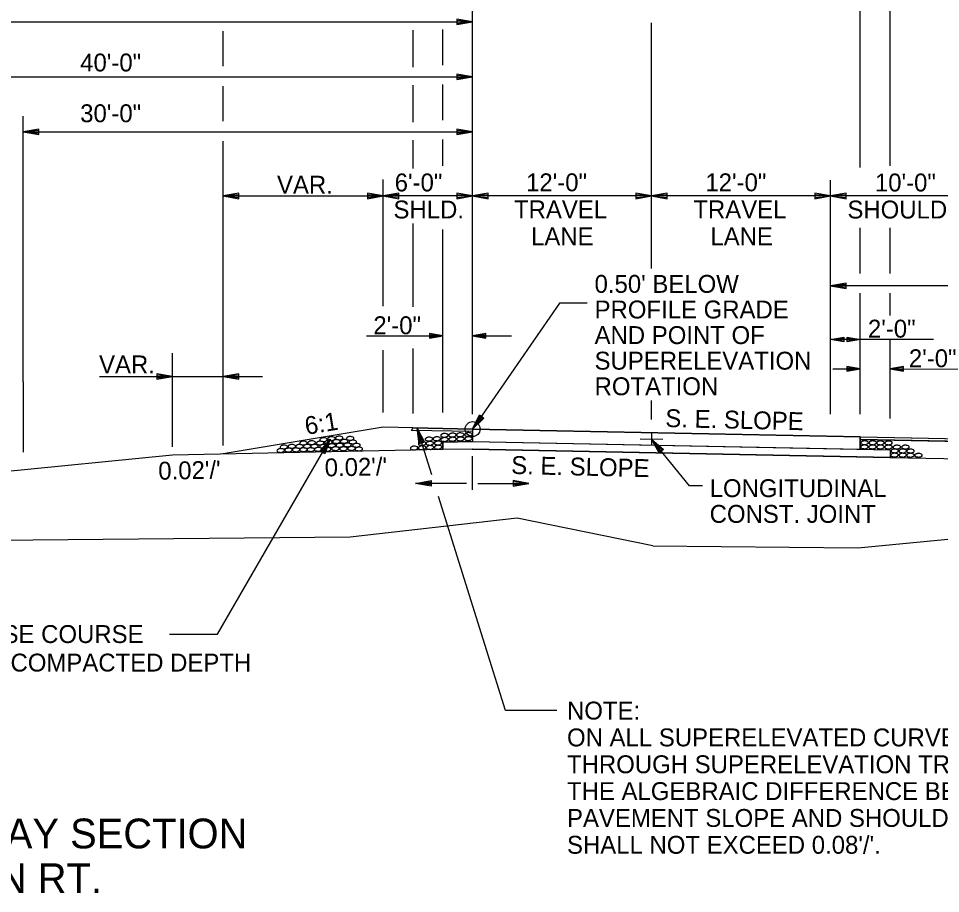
# Model space of a CAD drawing. Extents: x 1734743 to 1735935, y 759845 to 763831.
# Drawn here: x 1735753.6 to 1735815.4, y 760275.4 to 760334.1 of the extents above; entities that cross this region are included whole.
import ezdxf

# ---------------------------------------------------------------- set-up
doc = ezdxf.new("R2010")
doc.units = 0
for name, color, linetype in [('1', 7, 'Continuous'), ('10', 7, 'Continuous'), ('11', 7, 'Continuous'), ('19', 7, 'Continuous'), ('7', 7, 'Continuous'), ('8', 7, 'Continuous'), ('9', 7, 'Continuous'), ('Level 1', 7, 'Continuous'), ('R_Draft', 7, 'Continuous'), ('R_Prop Surface', 7, 'Continuous')]:
    doc.layers.add(name, color=color, linetype=linetype)

# ---------------------------------------------------------------- blocks, each defined once
blk = doc.blocks.new('TM')
at = {"layer": '8'}
for p, q in [((-120.309, 21.181), (-119.787, -20.829)), ((0, 0), (-120.309, 21.181)), ((-31.382, 2.945), (-120.176, 10.512)), ((-119.787, -20.829), (0, 0)), ((-119.911, -10.826), (-31.307, -3.057))]:
    blk.add_line(p, q, dxfattribs=at)
blk = doc.blocks.new('ROCKS')
at = {"layer": '1'}
blk.add_spline([(0.013, 0.06), (0.053, 0.053), (0.107, 0.033), (0.133, 0.013), (0.133, -0.007), (0.12, -0.033), (0.107, -0.04), (0.073, -0.053), (0.033, -0.067), (0.013, -0.067), (-0.02, -0.06), (-0.06, -0.053), (-0.087, -0.047), (-0.113, -0.02), (-0.113, -0.007), (-0.107, 0.02), (-0.087, 0.033), (-0.067, 0.047), (-0.033, 0.053), (-0.02, 0.06), (0.013, 0.06)], degree=3, dxfattribs=at)

msp = doc.modelspace()

# ---------------------------------------------------------------- linework, layer by layer
at = {"layer": '11'}
for p, q in [((1735787.06, 760300.552), (1735775.872, 760299.284)), ((1735796.16, 760298.685), (1735787.06, 760300.552)), ((1735775.872, 760299.284), (1735746.283, 760298.983)), ((1735809.903, 760298.57), (1735818.755, 760299.405)), ((1735796.16, 760298.685), (1735809.903, 760298.57))]:
    msp.add_line(p, q, dxfattribs=at)
at = {"layer": '19'}
for p, q in [((1735812.065, 760324.185), (1735812.065, 760345.329)), ((1735784.076, 760312.704), (1735784.076, 760335.65)), ((1735810.065, 760324.054), (1735810.065, 760335.441)), ((1735784.076, 760326.452), (1735784.076, 760334.485)), ((1735704.076, 760333.825), (1735784.076, 760333.825)), ((1735783.026, 760334.009), (1735783.026, 760333.642)), ((1735784.076, 760333.825), (1735783.026, 760334.009)), ((1735783.796, 760333.852), (1735783.026, 760333.913)), ((1735783.026, 760333.642), (1735784.076, 760333.825)), ((1735783.026, 760333.729), (1735783.796, 760333.799)), ((1735767.346, 760330.866), (1735767.346, 760333.195)), ((1735780.08, 760330.872), (1735780.08, 760333.281)), ((1735780.08, 760330.798), (1735780.08, 760333.127)), ((1735782.077, 760330.915), (1735782.077, 760333.324)), ((1735744.076, 760330.139), (1735784.076, 760330.139)), ((1735783.026, 760330.323), (1735783.026, 760329.955)), ((1735784.076, 760330.139), (1735783.026, 760330.323)), ((1735783.796, 760330.165), (1735783.026, 760330.226)), ((1735783.026, 760329.955), (1735784.076, 760330.139)), ((1735783.026, 760330.043), (1735783.796, 760330.113)), ((1735767.346, 760327.179), (1735767.346, 760329.508)), ((1735780.08, 760327.186), (1735780.08, 760329.594)), ((1735780.08, 760327.111), (1735780.08, 760329.44)), ((1735782.077, 760327.228), (1735782.077, 760329.637)), ((1735753.951, 760309.697), (1735753.951, 760327.498)), ((1735755.001, 760326.636), (1735753.951, 760326.452)), ((1735753.951, 760326.452), (1735755.001, 760326.268)), ((1735753.951, 760326.452), (1735784.076, 760326.452)), ((1735755.001, 760326.539), (1735754.231, 760326.478)), ((1735754.231, 760326.426), (1735755.001, 760326.356)), ((1735755.001, 760326.268), (1735755.001, 760326.636)), ((1735783.026, 760326.636), (1735783.026, 760326.268)), ((1735784.076, 760326.452), (1735783.026, 760326.636)), ((1735783.796, 760326.478), (1735783.026, 760326.54)), ((1735783.026, 760326.268), (1735784.076, 760326.452)), ((1735783.026, 760326.356), (1735783.796, 760326.426)), ((1735767.346, 760311.729), (1735767.346, 760325.822)), ((1735780.08, 760324.123), (1735780.08, 760325.89)), ((1735780.08, 760324.005), (1735780.08, 760325.754)), ((1735782.077, 760324.166), (1735782.077, 760325.933)), ((1735768.396, 760322.337), (1735767.346, 760322.153)), ((1735767.346, 760322.153), (1735768.396, 760321.97)), ((1735768.396, 760322.241), (1735767.626, 760322.18)), ((1735767.626, 760322.127), (1735768.396, 760322.057)), ((1735768.396, 760321.97), (1735768.396, 760322.337)), ((1735777.026, 760322.337), (1735777.026, 760321.97)), ((1735778.076, 760322.154), (1735777.026, 760322.337)), ((1735777.796, 760322.18), (1735777.026, 760322.241)), ((1735777.026, 760321.97), (1735778.076, 760322.154)), ((1735777.026, 760322.057), (1735777.796, 760322.127)), ((1735779.126, 760322.336), (1735778.076, 760322.153)), ((1735778.076, 760322.153), (1735779.126, 760321.969)), ((1735779.126, 760322.249), (1735778.356, 760322.179)), ((1735778.356, 760322.127), (1735779.126, 760322.065)), ((1735779.126, 760321.969), (1735779.126, 760322.336)), ((1735783.026, 760322.337), (1735783.026, 760321.969)), ((1735784.076, 760322.153), (1735783.026, 760322.337)), ((1735783.796, 760322.179), (1735783.026, 760322.24)), ((1735783.026, 760321.969), (1735784.076, 760322.153)), ((1735783.026, 760322.057), (1735783.796, 760322.127)), ((1735785.126, 760322.336), (1735784.076, 760322.153)), ((1735784.076, 760322.153), (1735785.126, 760321.969)), ((1735785.126, 760322.24), (1735784.356, 760322.179)), ((1735784.356, 760322.127), (1735785.126, 760322.056)), ((1735785.126, 760321.969), (1735785.126, 760322.336)), ((1735795.026, 760322.337), (1735795.026, 760321.969)), ((1735796.076, 760322.153), (1735795.026, 760322.337)), ((1735795.796, 760322.179), (1735795.026, 760322.24)), ((1735795.026, 760321.969), (1735796.076, 760322.153)), ((1735795.026, 760322.057), (1735795.796, 760322.127)), ((1735797.126, 760322.336), (1735796.076, 760322.153)), ((1735796.076, 760322.153), (1735797.126, 760321.969)), ((1735797.126, 760322.24), (1735796.356, 760322.179)), ((1735796.356, 760322.127), (1735797.126, 760322.056)), ((1735797.126, 760321.969), (1735797.126, 760322.336)), ((1735807.026, 760322.337), (1735807.026, 760321.969)), ((1735808.076, 760322.153), (1735807.026, 760322.337)), ((1735807.796, 760322.179), (1735807.026, 760322.24)), ((1735807.026, 760321.969), (1735808.076, 760322.153)), ((1735807.026, 760322.057), (1735807.796, 760322.127)), ((1735809.126, 760322.336), (1735808.076, 760322.153)), ((1735808.076, 760322.153), (1735809.126, 760321.969)), ((1735809.126, 760322.24), (1735808.356, 760322.179)), ((1735808.356, 760322.127), (1735809.126, 760322.056)), ((1735809.126, 760321.969), (1735809.126, 760322.336)), ((1735780.08, 760314.717), (1735780.08, 760320.307)), ((1735782.077, 760307.636), (1735782.077, 760319.912)), ((1735810.065, 760316.957), (1735810.065, 760320.014)), ((1735812.065, 760316.957), (1735812.065, 760320.014)), ((1735809.126, 760316.308), (1735808.076, 760316.124)), ((1735808.076, 760316.124), (1735809.126, 760315.94)), ((1735809.126, 760316.212), (1735808.356, 760316.15)), ((1735808.356, 760316.098), (1735809.126, 760316.028)), ((1735809.126, 760315.94), (1735809.126, 760316.308)), ((1735810.068, 760313.588), (1735810.068, 760315.646)), ((1735812.068, 760314.129), (1735812.068, 760315.646)), ((1735810.068, 760307.517), (1735810.068, 760313.588)), ((1735776.968, 760312.766), (1735782.077, 760312.766)), ((1735781.182, 760312.923), (1735781.182, 760312.61)), ((1735782.077, 760312.766), (1735781.182, 760312.923)), ((1735781.838, 760312.788), (1735781.182, 760312.841)), ((1735781.182, 760312.61), (1735782.077, 760312.766)), ((1735781.182, 760312.684), (1735781.838, 760312.744)), ((1735784.971, 760312.924), (1735784.076, 760312.767)), ((1735784.076, 760312.767), (1735786.681, 760312.766)), ((1735784.076, 760312.767), (1735784.971, 760312.611)), ((1735784.971, 760312.849), (1735784.315, 760312.79)), ((1735784.315, 760312.745), (1735784.971, 760312.693)), ((1735784.971, 760312.611), (1735784.971, 760312.924)), ((1735808.076, 760312.537), (1735808.971, 760312.694)), ((1735814.973, 760312.537), (1735808.076, 760312.537)), ((1735808.971, 760312.381), (1735808.076, 760312.537)), ((1735808.315, 760312.559), (1735808.971, 760312.612)), ((1735808.971, 760312.455), (1735808.315, 760312.515)), ((1735808.971, 760312.694), (1735808.971, 760312.381)), ((1735809.182, 760312.38), (1735809.182, 760312.694)), ((1735809.182, 760312.694), (1735810.076, 760312.537)), ((1735809.182, 760312.619), (1735809.838, 760312.559)), ((1735810.076, 760312.537), (1735809.182, 760312.38)), ((1735809.838, 760312.515), (1735809.182, 760312.462)), ((1735812.068, 760307.235), (1735812.068, 760312.499)), ((1735763.948, 760305.323), (1735763.948, 760311.62)), ((1735767.346, 760305.431), (1735767.346, 760311.729)), ((1735778.076, 760307.636), (1735778.076, 760311.818)), ((1735780.08, 760307.577), (1735780.08, 760311.917)), ((1735763.948, 760305.323), (1735763.948, 760311.081)), ((1735808.231, 760310.553), (1735810.068, 760310.553)), ((1735809.174, 760310.709), (1735809.174, 760310.396)), ((1735810.068, 760310.553), (1735809.174, 760310.709)), ((1735809.83, 760310.575), (1735809.174, 760310.627)), ((1735809.174, 760310.396), (1735810.068, 760310.553)), ((1735809.174, 760310.471), (1735809.83, 760310.53)), ((1735812.963, 760310.71), (1735812.068, 760310.554)), ((1735812.068, 760310.554), (1735817.745, 760310.55)), ((1735812.068, 760310.554), (1735812.963, 760310.397)), ((1735812.963, 760310.636), (1735812.307, 760310.576)), ((1735812.307, 760310.532), (1735812.963, 760310.479)), ((1735812.963, 760310.397), (1735812.963, 760310.71)), ((1735759.049, 760310.046), (1735769.982, 760310.046)), ((1735762.898, 760310.23), (1735762.898, 760309.862)), ((1735763.948, 760310.046), (1735762.898, 760310.23)), ((1735763.668, 760310.072), (1735762.898, 760310.133)), ((1735762.898, 760309.862), (1735763.948, 760310.046)), ((1735762.898, 760309.95), (1735763.668, 760310.02)), ((1735768.396, 760310.229), (1735767.346, 760310.046)), ((1735767.346, 760310.046), (1735768.396, 760309.862)), ((1735768.396, 760310.133), (1735767.626, 760310.072)), ((1735767.626, 760310.02), (1735768.396, 760309.949)), ((1735768.396, 760309.862), (1735768.396, 760310.229)), ((1735784.076, 760306.52), (1735784.54, 760307.48)), ((1735784.835, 760307.264), (1735784.076, 760306.52)), ((1735784.222, 760306.758), (1735784.613, 760307.421)), ((1735784.764, 760307.314), (1735784.262, 760306.73)), ((1735784.54, 760307.48), (1735784.835, 760307.264)), ((1735778.076, 760306.64), (1735767.346, 760304.852)), ((1735784.076, 760306.52), (1735778.076, 760306.64)), ((1735780.491, 760305.54), (1735780.357, 760306.594)), ((1735780.357, 760306.594), (1735780.841, 760305.644)), ((1735784.076, 760306.353), (1735779.982, 760306.435)), ((1735780.573, 760305.566), (1735780.412, 760306.319)), ((1735780.459, 760306.334), (1735780.75, 760305.622)), ((1735784.076, 760306.52), (1735818.08, 760305.84)), ((1735784.076, 760306.52), (1735784.076, 760305.686)), ((1735810.068, 760306), (1735810.068, 760305.166)), ((1735766.973, 760292.777), (1735774.532, 760305.855)), ((1735773.85, 760305.04), (1735774.532, 760305.855)), ((1735773.925, 760304.997), (1735774.368, 760305.628)), ((1735774.411, 760305.603), (1735774.087, 760304.905)), ((1735774.532, 760305.855), (1735774.165, 760304.854)), ((1735780.841, 760305.644), (1735780.491, 760305.54)), ((1735784.076, 760305.686), (1735782.077, 760305.646)), ((1735782.077, 760305.646), (1735782.077, 760305.146)), ((1735784.076, 760305.686), (1735810.068, 760305.166)), ((1735796.593, 760304.925), (1735796.076, 760305.854)), ((1735796.076, 760305.854), (1735796.879, 760305.152)), ((1735796.66, 760304.98), (1735796.23, 760305.619)), ((1735796.268, 760305.651), (1735796.803, 760305.098)), ((1735810.068, 760305.833), (1735818.164, 760305.671)), ((1735763.948, 760304.784), (1735741.106, 760302.499)), ((1735763.948, 760304.784), (1735741.106, 760302.499)), ((1735782.077, 760305.146), (1735763.948, 760304.784)), ((1735774.165, 760304.854), (1735773.85, 760305.04)), ((1735784.04, 760305.185), (1735782.04, 760305.145)), ((1735784.076, 760305.186), (1735782.077, 760305.146)), ((1735784.04, 760305.185), (1735812.05, 760304.625)), ((1735784.04, 760304.713), (1735784.04, 760302.459)), ((1735796.879, 760305.152), (1735796.593, 760304.925)), ((1735810.068, 760305.166), (1735812.068, 760305.126)), ((1735812.068, 760305.126), (1735812.068, 760304.626)), ((1735812.05, 760304.625), (1735830.581, 760304.255)), ((1735783.661, 760302.876), (1735780.24, 760302.876)), ((1735784.419, 760302.876), (1735787.84, 760302.876)), ((1735763.741, 760292.777), (1735766.973, 760292.777))]:
    msp.add_line(p, q, dxfattribs=at)
for points in [[(1735784.076, 760306.353), (1735779.982, 760306.435), (1735779.982, 760306.435), (1735780.077, 760306.6), (1735780.077, 760306.6), (1735780.077, 760306.6), (1735784.076, 760306.52), (1735784.076, 760306.52), (1735784.076, 760306.52), (1735784.076, 760306.353), (1735784.076, 760306.353), (1735784.076, 760306.353)], [(1735818.164, 760305.671), (1735810.068, 760305.833), (1735810.068, 760305.833), (1735810.068, 760306), (1735810.068, 760306), (1735810.068, 760306), (1735818.08, 760305.84), (1735818.08, 760305.84), (1735818.08, 760305.84), (1735818.164, 760305.671), (1735818.164, 760305.671), (1735818.164, 760305.671)], [(1735782.077, 760305.146), (1735782.077, 760305.646), (1735784.076, 760305.686), (1735812.068, 760305.126), (1735812.068, 760304.626), (1735812.068, 760304.626), (1735812.068, 760304.626), (1735784.076, 760305.186), (1735782.077, 760305.146)], [(1735799.482, 760302.726), (1735798.606, 760302.726), (1735796.076, 760305.854)]]:
    msp.add_lwpolyline(points, dxfattribs=at)
msp.add_lwpolyline([(1735810.068, 760306), (1735784.076, 760306.52), (1735784.076, 760305.686), (1735810.068, 760305.166)], close=True, dxfattribs=at)
at = {"layer": '7'}
for p, q in [((1735796.076, 760317.3), (1735796.076, 760333.765)), ((1735796.076, 760307.168), (1735796.076, 760308.435))]:
    msp.add_line(p, q, dxfattribs=at)
at = {"layer": '9'}
for p, q in [((1735784.076, 760307.518), (1735784.076, 760326.452)), ((1735778.076, 760314.759), (1735778.076, 760323.264)), ((1735808.076, 760307.512), (1735808.076, 760323.203)), ((1735767.346, 760322.153), (1735778.076, 760322.153)), ((1735784.076, 760322.153), (1735778.076, 760322.153)), ((1735796.076, 760322.153), (1735784.076, 760322.153)), ((1735808.076, 760322.153), (1735796.076, 760322.153)), ((1735818.066, 760322.153), (1735808.076, 760322.153)), ((1735838.118, 760316.124), (1735808.076, 760316.124)), ((1735753.951, 760309.697), (1735753.951, 760304.969)), ((1735781.336, 760303.45), (1735780.357, 760306.594)), ((1735786.28, 760287.646), (1735781.79, 760301.998))]:
    msp.add_line(p, q, dxfattribs=at)
for points in [[(1735791.752, 760314.963), (1735789.907, 760314.963), (1735784.076, 760306.52)], [(1735789.714, 760287.646), (1735786.28, 760287.646)]]:
    msp.add_lwpolyline(points, dxfattribs=at)
msp.add_circle((1735784.076, 760306.52), 0.5, dxfattribs=at)
at = {"layer": 'R_Draft'}
for p, q in [((1735796.076, 760306.229), (1735796.076, 760305.478)), ((1735795.305, 760305.869), (1735796.824, 760305.839))]:
    msp.add_line(p, q, dxfattribs=at)
at = {"layer": 'R_Prop Surface'}
msp.add_line((1735780.077, 760306.6), (1735779.982, 760306.435), dxfattribs=at)

# ---------------------------------------------------------------- block references
at = {"layer": '19', "xscale": 0.008761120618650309}
for p, yscale, rotation in [((1735780.236, 760302.871), -0.008761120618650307, -179.20057588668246), ((1735787.84, 760302.871), 0.008761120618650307, -0.7994241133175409)]:
    msp.add_blockref('TM', p, dxfattribs=dict(at, yscale=yscale, rotation=rotation))
at = {"layer": 'Level 1'}
for p, xscale, yscale, rotation in [((1735774.066, 760305.82), 2.011654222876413, 2.011654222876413, 1.8263814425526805), ((1735774.594, 760305.892), 2.011654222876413, 2.011654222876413, 1.8263814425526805), ((1735775.112, 760305.931), 2.011654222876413, 2.011654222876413, 1.8263814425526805), ((1735775.851, 760305.903), 2.011654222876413, 2.011654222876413, 1.8263814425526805), ((1735781.129, 760305.86), 2.0116542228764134, 2.011654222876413, 3.8532744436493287), ((1735781.656, 760305.878), 2.0116542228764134, 2.011654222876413, 3.8532744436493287), ((1735782.166, 760306.108), 2.0116542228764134, 2.011654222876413, 3.8532744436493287), ((1735782.171, 760305.828), 2.0116542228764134, 2.011654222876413, 3.8532744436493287), ((1735782.709, 760306.128), 2.0116542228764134, 2.011654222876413, 3.8532744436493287), ((1735782.713, 760305.848), 2.0116542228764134, 2.011654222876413, 3.8532744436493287), ((1735783.23, 760306.146), 2.0116542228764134, 2.011654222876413, 3.8532744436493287), ((1735783.235, 760305.866), 2.0116542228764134, 2.011654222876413, 3.8532744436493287), ((1735783.773, 760306.165), 2.0116542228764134, 2.011654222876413, 3.8532744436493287), ((1735783.777, 760305.885), 2.0116542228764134, 2.011654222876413, 3.8532744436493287), ((1735771.406, 760305.329), 2.011654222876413, 2.011654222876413, 1.8263814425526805), ((1735771.931, 760305.369), 2.011654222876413, 2.011654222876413, 1.8263814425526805), ((1735772.443, 760305.369), 2.011654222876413, 2.011654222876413, 1.8263814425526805), ((1735772.709, 760305.592), 2.011654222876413, 2.011654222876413, 1.8263814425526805), ((1735772.953, 760305.369), 2.011654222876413, 2.011654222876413, 1.8263814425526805), ((1735773.263, 760305.616), 2.011654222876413, 2.011654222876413, 1.8263814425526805), ((1735773.446, 760305.375), 2.011654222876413, 2.011654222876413, 1.8263814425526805), ((1735773.698, 760305.17), 2.011654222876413, 2.011654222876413, 1.8263814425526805), ((1735773.837, 760305.589), 2.011654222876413, 2.011654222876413, 1.8263814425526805), ((1735774.054, 760305.375), 2.011654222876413, 2.011654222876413, 1.8263814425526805), ((1735774.306, 760305.17), 2.011654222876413, 2.011654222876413, 1.8263814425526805), ((1735774.39, 760305.637), 2.011654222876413, 2.011654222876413, 1.8263814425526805), ((1735774.608, 760305.422), 2.011654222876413, 2.011654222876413, 1.8263814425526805), ((1735774.86, 760305.217), 2.011654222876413, 2.011654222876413, 1.8263814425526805), ((1735774.923, 760305.696), 2.011654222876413, 2.011654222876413, 1.8263814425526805), ((1735775.142, 760305.442), 2.011654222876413, 2.011654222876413, 1.8263814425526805), ((1735775.4, 760305.205), 2.011654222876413, 2.011654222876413, 1.8263814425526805), ((1735775.45, 760305.71), 2.011654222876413, 2.011654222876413, 1.8263814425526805), ((1735775.673, 760305.467), 2.011654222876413, 2.011654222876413, 1.8263814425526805), ((1735775.936, 760305.229), 2.011654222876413, 2.011654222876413, 1.8263814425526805), ((1735776.024, 760305.663), 2.011654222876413, 2.011654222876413, 1.8263814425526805), ((1735776.269, 760305.445), 2.011654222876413, 2.011654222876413, 1.8263814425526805), ((1735776.432, 760305.192), 2.011654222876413, 2.011654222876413, 1.8263814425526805), ((1735780.134, 760305.256), 2.0116542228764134, 2.011654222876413, 3.8532744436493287), ((1735780.672, 760305.555), 2.0116542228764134, 2.011654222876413, 3.8532744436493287), ((1735780.677, 760305.275), 2.0116542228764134, 2.011654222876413, 3.8532744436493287), ((1735781.193, 760305.574), 2.0116542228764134, 2.011654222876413, 3.8532744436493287), ((1735781.198, 760305.294), 2.0116542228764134, 2.011654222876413, 3.8532744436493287), ((1735781.736, 760305.593), 2.0116542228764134, 2.011654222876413, 3.8532744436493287), ((1735781.74, 760305.313), 2.0116542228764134, 2.011654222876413, 3.8532744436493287), ((1735810.329, 760305.334), 2.011654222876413, 2.011654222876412, 1.33680650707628), ((1735810.337, 760305.614), 2.011654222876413, 2.011654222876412, 1.33680650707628), ((1735810.873, 760305.33), 2.011654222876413, 2.011654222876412, 1.33680650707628), ((1735810.88, 760305.61), 2.011654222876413, 2.011654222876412, 1.33680650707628), ((1735811.394, 760305.325), 2.011654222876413, 2.011654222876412, 1.33680650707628), ((1735811.402, 760305.605), 2.011654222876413, 2.011654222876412, 1.33680650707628), ((1735811.937, 760305.321), 2.011654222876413, 2.011654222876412, 1.33680650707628), ((1735811.945, 760305.601), 2.011654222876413, 2.011654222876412, 1.33680650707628), ((1735812.505, 760305.321), 2.011654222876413, 2.011654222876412, 1.33680650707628), ((1735813.075, 760305.321), 2.011654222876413, 2.011654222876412, 1.33680650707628), ((1735771.186, 760305.092), 2.011654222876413, 2.011654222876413, 1.8263814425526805), ((1735771.716, 760305.122), 2.011654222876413, 2.011654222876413, 1.8263814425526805), ((1735772.215, 760305.136), 2.011654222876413, 2.011654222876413, 1.8263814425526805), ((1735772.711, 760305.146), 2.011654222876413, 2.011654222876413, 1.8263814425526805), ((1735773.208, 760305.154), 2.011654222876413, 2.011654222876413, 1.8263814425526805), ((1735812.346, 760304.785), 2.011654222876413, 2.011654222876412, 1.33680650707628), ((1735812.354, 760305.065), 2.011654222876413, 2.011654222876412, 1.33680650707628), ((1735812.89, 760304.781), 2.011654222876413, 2.011654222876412, 1.33680650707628), ((1735812.897, 760305.061), 2.011654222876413, 2.011654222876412, 1.33680650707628), ((1735813.411, 760304.776), 2.011654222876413, 2.011654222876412, 1.33680650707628), ((1735813.419, 760305.056), 2.011654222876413, 2.011654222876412, 1.33680650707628), ((1735813.954, 760304.772), 2.011654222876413, 2.011654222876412, 1.33680650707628)]:
    msp.add_blockref('ROCKS', p, dxfattribs=dict(at, xscale=xscale, yscale=yscale, rotation=rotation))

# ---------------------------------------------------------------- texts
at = {"layer": '10'}
for s, height, p in [('VAR.', 1.2, (1735770.96, 760322.307)), ('6\'-0"', 1.2, (1735778.851, 760322.459)), ('10\'-0"', 1.2, (1735811.047, 760322.456)), ('SHLD.', 1.2, (1735778.771, 760320.646)), ('SHOULDER', 1.2, (1735809.204, 760320.644)), ("0.50' BELOW", 1.2, (1735792.252, 760315.658)), ('PROFILE GRADE', 1.2, (1735792.252, 760313.941)), ('AND POINT OF', 1.2, (1735792.252, 760312.225)), ('SUPERELEVATION', 1.2, (1735792.252, 760310.509)), ('ROTATION  ', 1.2, (1735792.252, 760308.793)), ('NOTE:', 1.2, (1735790.404, 760287.046)), ('ON ALL SUPERELEVATED CURVES AND', 1.2, (1735790.404, 760285.246)), ('THROUGH SUPERELEVATION TRANSITIONS,', 1.2, (1735790.404, 760283.446)), ('THE ALGEBRAIC DIFFERENCE BETWEEN', 1.2, (1735790.404, 760281.646)), ('PAVEMENT SLOPE AND SHOULDER SLOPE', 1.2, (1735790.404, 760279.846)), ('I-57 TYPICAL DIVIDED HIGHWAY SECTION', 2, (1735714.734, 760278.405)), ("SHALL NOT EXCEED 0.08'/'.", 1.2, (1735790.404, 760278.046)), ('W/ SUPERELEVATION RT.', 2, (1735725.939, 760275.405))]:
    msp.add_text(s, height=height, dxfattribs=at).set_placement(p)
for s, rotation, p in [('S. E. SLOPE', 358.63856, (1735796.985, 760306.663)), ("0.02'/'", 1.0121, (1735774.167, 760303.347)), ('S. E. SLOPE', 358.63856, (1735786.65, 760303.516)), ("0.02'/'", 1.0121, (1735763.01, 760303.124))]:
    msp.add_text(s, height=1.2, rotation=rotation, dxfattribs=at).set_placement(p)
at = {"layer": '19'}
for s, p in [('40\'-0"', (1735757.764, 760330.503)), ('30\'-0"', (1735757.764, 760327.099)), ('12\'-0"', (1735787.658, 760322.468)), ('12\'-0"', (1735799.681, 760322.468)), ('TRAVEL', (1735786.85, 760320.655)), ('TRAVEL', (1735798.873, 760320.655)), ('LANE', (1735787.994, 760318.843)), ('LANE', (1735800.017, 760318.843)), ('2\'-0"', (1735777.419, 760312.884)), ('2\'-0"', (1735810.58, 760312.655)), ('2\'-0"', (1735813.325, 760310.671)), ('VAR.', (1735759.029, 760310.258)), ('LONGITUDINAL', (1735799.968, 760301.96)), ('CONST. JOINT', (1735799.968, 760300.235))]:
    msp.add_text(s, height=1.2, dxfattribs=at).set_placement(p)
for s, rotation, p in [('6:1', 9.45113, (1735772.926, 760306.129)), ('AGGREGATE BASE COURSE', 360, (1735739.808, 760292.177)), ('(CLASS 7) - VAR. COMPACTED DEPTH', 360, (1735739.808, 760290.265))]:
    msp.add_text(s, height=1.2, rotation=rotation, dxfattribs=at).set_placement(p)

doc.saveas('drawing.dxf')
